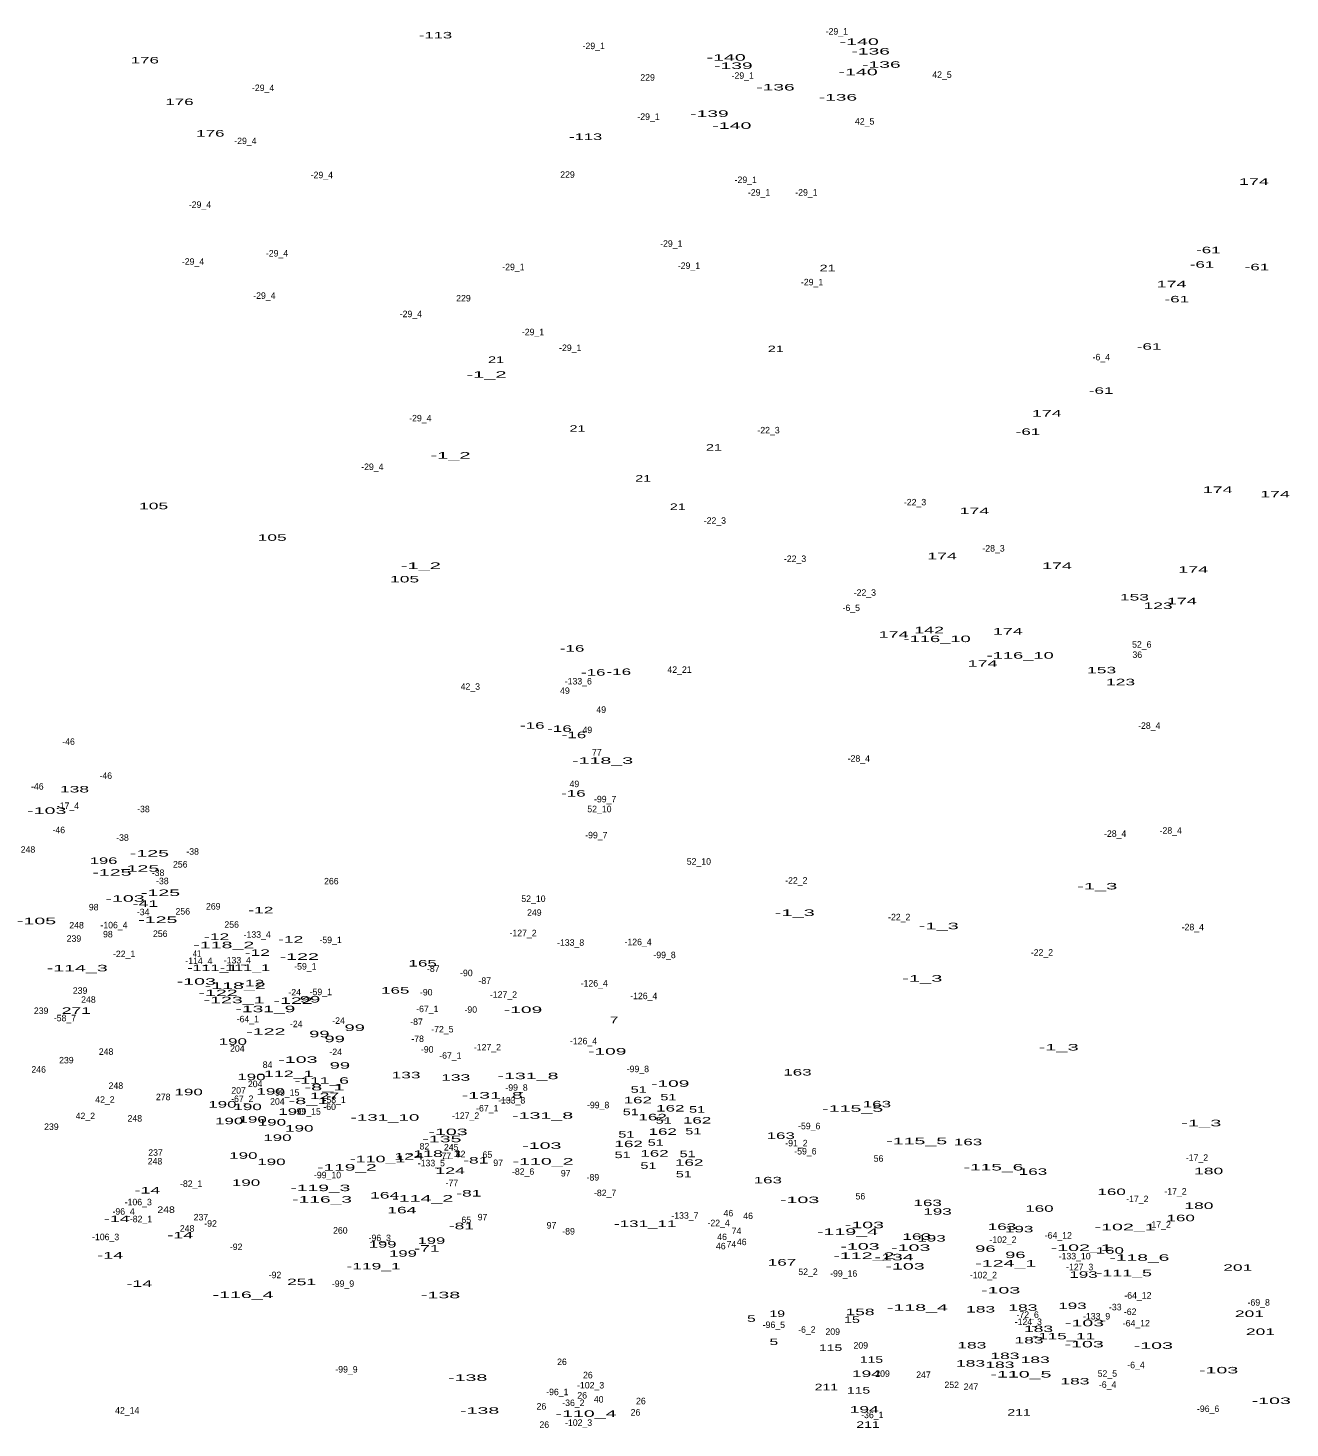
# Model space of a CAD drawing. Extents: x -656096 to -652763, y -1002270 to -998958.
# Drawn here: x -655334 to -654559, y -1000715 to -999855 of the extents above; entities that cross this region are included whole.
import ezdxf
from ezdxf.enums import TextEntityAlignment as Align

# ---------------------------------------------------------------- set-up
doc = ezdxf.new("R2010")
doc.units = 0
doc.header["$LTSCALE"] = 1.6
doc.layers.add('24', color=7, linetype='Continuous')

msp = doc.modelspace()

# ---------------------------------------------------------------- texts
at = {"layer": '24'}
for s, p in [('-29_1', (-654837.412, -999859.48)), ('-29_1', (-654986.682, -999868.4)), ('42_5', (-654772.83, -999886.05)), ('-29_4', (-655189.722, -999894.15)), ('229', (-654953.613, -999887.77)), ('-29_1', (-654895.182, -999886.63)), ('-29_1', (-654953.032, -999911.84)), ('42_5', (-654820.32, -999914.75)), ('-29_4', (-655200.582, -999926.73)), ('-29_4', (-655153.662, -999947.68)), ('229', (-655002.793, -999947.43)), ('-29_1', (-654893.322, -999950.63)), ('-29_1', (-654885.172, -999958.39)), ('-29_1', (-654856.092, -999958.39)), ('-29_4', (-655228.502, -999965.91)), ('-29_4', (-655181.192, -999995.77)), ('-29_1', (-654939.072, -999989.8)), ('-29_4', (-655232.762, -1000000.82)), ('-29_1', (-655036.002, -1000004.16)), ('-29_1', (-654928.212, -1000003.38)), ('-29_1', (-654852.602, -1000013.47)), ('-29_4', (-655188.952, -1000021.76)), ('229', (-655066.693, -1000023.36)), ('-29_4', (-655098.992, -1000033.01)), ('-29_1', (-655023.982, -1000044.11)), ('-29_1', (-655001.112, -1000053.8)), ('-6_4', (-654674.983, -1000059.52)), ('-29_4', (-655093.182, -1000097.01)), ('-22_3', (-654879.332, -1000104.38)), ('-29_4', (-655122.642, -1000126.88)), ('-22_3', (-654789.382, -1000148.6)), ('-22_3', (-654912.292, -1000159.9)), ('-28_3', (-654741.182, -1000176.93)), ('-22_3', (-654863.052, -1000183.36)), ('-22_3', (-654820.202, -1000204.12)), ('-6_5', (-654828.539, -1000213.49)), ('52_6', (-654650.14, -1000235.97)), ('36', (-654652.903, -1000242.28)), ('42_21', (-654934.003, -1000251.42)), ('42_3', (-655062.45, -1000261.81)), ('-133_6', (-654996.162, -1000258.56)), ('49', (-655004.377, -1000264.39)), ('49', (-654982.087, -1000276.02)), ('49', (-654990.617, -1000288.44)), ('-28_4', (-654645.547, -1000285.82)), ('-46', (-655309.195, -1000295.64)), ('77', (-654984.779, -1000302.23)), ('-28_4', (-654823.897, -1000305.99)), ('-46', (-655328.365, -1000323.15)), ('-46', (-655286.345, -1000316.56)), ('49', (-654998.567, -1000321.6)), ('-99_7', (-654979.668, -1000330.95)), ('-17_4', (-655309.566, -1000335.02)), ('-38', (-655263.215, -1000337.04)), ('52_10', (-654983.193, -1000337.04)), ('-46', (-655315.195, -1000349.88)), ('-28_4', (-654632.357, -1000350.21)), ('-38', (-655276.085, -1000354.57)), ('-99_7', (-654985.088, -1000353.06)), ('-28_4', (-654666.477, -1000352.14)), ('248', (-655334.091, -1000361.9)), ('-38', (-655233.005, -1000363.1)), ('256', (-655240.593, -1000371)), ('52_10', (-654922.123, -1000369.24)), ('-38', (-655254.205, -1000376.17)), ('-38', (-655251.595, -1000381.21)), ('266', (-655147.818, -1000381.35)), ('-22_2', (-654862.292, -1000380.9)), ('52_10', (-655023.703, -1000392.12)), ('98', (-655293.763, -1000397.31)), ('-34', (-655263.379, -1000400.27)), ('256', (-655239.043, -1000399.86)), ('269', (-655220.318, -1000396.79)), ('249', (-655023.157, -1000400.63)), ('248', (-655304.271, -1000408.39)), ('-106_4', (-655281.3, -1000408.31)), ('256', (-655209.033, -1000407.99)), ('-22_2', (-654799.092, -1000403.4)), ('-28_4', (-654618.787, -1000409.55)), ('239', (-655305.883, -1000416.57)), ('98', (-655285.043, -1000413.89)), ('256', (-655252.883, -1000413.61)), ('-133_4', (-655193.35, -1000414.09)), ('-59_1', (-655148.282, -1000417.42)), ('-127_2', (-655030.092, -1000413.2)), ('-133_8', (-655000.856, -1000419.04)), ('-126_4', (-654959.456, -1000418.69)), ('-22_1', (-655275.066, -1000425.99)), ('-99_8', (-654943.203, -1000426.64)), ('-22_2', (-654711.462, -1000425.12)), ('-114_4', (-655229.168, -1000430.28)), ('-133_4', (-655205.55, -1000429.88)), ('-59_1', (-655163.772, -1000433.68)), ('-87', (-655085.221, -1000435.08)), ('-90', (-655064.914, -1000437.71)), ('-87', (-655053.621, -1000442.45)), ('-126_4', (-654986.376, -1000444.07)), ('239', (-655302.103, -1000448.53)), ('-24', (-655170.329, -1000449.52)), ('-59_1', (-655154.292, -1000449.37)), ('-90', (-655089.544, -1000449.54)), ('-127_2', (-655042.102, -1000450.97)), ('-126_4', (-654955.976, -1000451.82)), ('239', (-655326.023, -1000460.93)), ('248', (-655296.971, -1000454.04)), ('-67_1', (-655088.867, -1000459.77)), ('-90', (-655062.204, -1000460.2)), ('-58_7', (-655311.408, -1000465.41)), ('-64_1', (-655199.116, -1000466.01)), ('-24', (-655169.359, -1000469.01)), ('-24', (-655143.379, -1000466.98)), ('-87', (-655095.491, -1000467.66)), ('-78', (-655094.831, -1000478.13)), ('-72_5', (-655079.638, -1000472.25)), ('248', (-655286.131, -1000486.01)), ('204', (-655205.545, -1000484.06)), ('-24', (-655145.129, -1000486.18)), ('-90', (-655088.954, -1000484.64)), ('-127_2', (-655051.982, -1000483.32)), ('-126_4', (-654992.956, -1000479.52)), ('239', (-655310.533, -1000491.27)), ('84', (-655187.001, -1000494.07)), ('-67_1', (-655074.727, -1000488.44)), ('246', (-655327.547, -1000496.94)), ('-99_8', (-654959.583, -1000496.65)), ('248', (-655280.131, -1000506.93)), ('207', (-655204.777, -1000509.81)), ('204', (-655194.605, -1000505.85)), ('-99_15', (-655175.777, -1000511.14)), ('-99_8', (-655034.093, -1000508.05)), ('42_2', (-655286.84, -1000515.42)), ('278', (-655251.063, -1000513.86)), ('-67_2', (-655202.494, -1000514.97)), ('204', (-655180.955, -1000516.6)), ('-60', (-655148.854, -1000519.88)), ('-58_1', (-655145.786, -1000515.57)), ('-67_1', (-655052.077, -1000520.79)), ('-133_8', (-655037.066, -1000515.89)), ('-99_8', (-654983.983, -1000518.82)), ('42_2', (-655298.86, -1000525.5)), ('248', (-655268.511, -1000526.99)), ('-99_15', (-655162.597, -1000522.78)), ('-127_2', (-655065.342, -1000525.36)), ('239', (-655319.723, -1000532.12)), ('-59_6', (-654854.373, -1000531.7)), ('237', (-655255.773, -1000547.98)), ('82', (-655090.657, -1000544.14)), ('245', (-655074.201, -1000544.76)), ('-91_2', (-654862.202, -1000542.21)), ('-59_6', (-654856.693, -1000547.2)), ('248', (-655256.121, -1000553.33)), ('-133_5', (-655086.416, -1000554.46)), ('-77', (-655078.085, -1000550.04)), ('82', (-655068.457, -1000548.89)), ('65', (-655051.983, -1000549.26)), ('97', (-655045.398, -1000554.29)), ('56', (-654811.793, -1000551.65)), ('-17_2', (-654616.252, -1000551.07)), ('-99_10', (-655150.161, -1000561.8)), ('-82_6', (-655030.038, -1000559.68)), ('97', (-655003.908, -1000560.69)), ('-89', (-654987.2, -1000563.2)), ('-82_1', (-655233.896, -1000567.11)), ('-77', (-655073.815, -1000566.72)), ('-82_7', (-654979.688, -1000572.77)), ('-17_2', (-654629.442, -1000571.82)), ('-106_3', (-655266.396, -1000578.42)), ('56', (-654822.943, -1000574.82)), ('-17_2', (-654652.902, -1000576.47)), ('-96_4', (-655275.378, -1000584.17)), ('-82_1', (-655264.716, -1000588.82)), ('237', (-655227.893, -1000587.69)), ('65', (-655064.973, -1000589.31)), ('97', (-655054.988, -1000587.65)), ('-133_7', (-654930.692, -1000586.64)), ('46', (-654903.997, -1000585.21)), ('46', (-654891.877, -1000586.86)), ('248', (-655236.371, -1000594.59)), ('-92', (-655221.99, -1000591.55)), ('260', (-655142.297, -1000595.81)), ('97', (-655012.628, -1000592.69)), ('-89', (-655002.13, -1000596.37)), ('-22_4', (-654909.987, -1000591.24)), ('74', (-654899.007, -1000596.11)), ('-64_12', (-654701.386, -1000598.86)), ('-17_2', (-654639.132, -1000592.18)), ('-106_3', (-655286.436, -1000599.82)), ('-92', (-655206.29, -1000605.9)), ('-96_3', (-655118.093, -1000600.41)), ('46', (-654908.657, -1000605.43)), ('46', (-654907.877, -1000599.76)), ('74', (-654902.157, -1000604.31)), ('46', (-654895.807, -1000602.87)), ('-102_2', (-654735.37, -1000601.5)), ('-133_10', (-654691.363, -1000611.62)), ('-92', (-655182.44, -1000623.16)), ('52_2', (-654855.095, -1000621.21)), ('-99_16', (-654833.182, -1000622.25)), ('-102_2', (-654747.39, -1000623.22)), ('-127_3', (-654688.282, -1000618.3)), ('-99_9', (-655140.658, -1000628.48)), ('-64_12', (-654652.516, -1000635.73)), ('-69_8', (-654578.343, -1000640.02)), ('-72_6', (-654720.224, -1000647.55)), ('-133_9', (-654677.882, -1000648.52)), ('-33', (-654666.415, -1000642.9)), ('-62', (-654657.26, -1000645.76)), ('-96_5', (-654876.073, -1000653.77)), ('-6_2', (-654855.799, -1000656.69)), ('209', (-654839.927, -1000657.99)), ('-124_3', (-654719.82, -1000651.93)), ('-64_12', (-654653.486, -1000652.79)), ('209', (-654822.697, -1000666.41)), ('26', (-655006.193, -1000676.51)), ('-99_9', (-655138.528, -1000681.12)), ('26', (-654990.303, -1000684.65)), ('209', (-654809.337, -1000683.75)), ('247', (-654784.187, -1000684.44)), ('52_5', (-654671.275, -1000683.69)), ('-6_4', (-654653.683, -1000678.48)), ('-102_3', (-654988.6, -1000690.88)), ('252', (-654766.837, -1000690.65)), ('247', (-654755.037, -1000691.8)), ('-6_4', (-654671.123, -1000690.5)), ('-96_1', (-655009.047, -1000695.01)), ('-36_2', (-654999.168, -1000701.68)), ('26', (-654993.793, -1000697.07)), ('40', (-654983.655, -1000699.56)), ('26', (-654957.733, -1000700.56)), ('42_14', (-655273.158, -1000706.35)), ('26', (-655018.793, -1000703.85)), ('26', (-654961.023, -1000707.54)), ('-36_1', (-654815.622, -1000709.11)), ('-96_6', (-654609.408, -1000705.33)), ('26', (-655017.053, -1000715.1)), ('-102_3', (-654995.97, -1000713.87))]:
    msp.add_text(s, height=4, dxfattribs=at).set_placement(p, align=Align.CENTER)
for s, width, p in [('-113', 1.9, (-655083.827, -999861.82)), ('-140', 2.25, (-654823.672, -999865.82)), ('176', 1.95, (-655262.387, -999877.19)), ('-140', 2.25, (-654905.382, -999875.51)), ('-136', 2.2, (-654816.595, -999871.71)), ('-139', 2.2, (-654900.905, -999880.56)), ('-140', 2.25, (-654824.342, -999884.42)), ('-136', 2.2, (-654810.015, -999879.84)), ('-136', 2.2, (-654875.075, -999893.79)), ('176', 1.95, (-655241.087, -999902.75)), ('-136', 2.2, (-654836.735, -999899.99)), ('-139', 2.2, (-654915.625, -999910)), ('-140', 2.25, (-654901.892, -999917.35)), ('176', 1.95, (-655222.107, -999922.12)), ('-113', 1.9, (-654991.657, -999924.19)), ('174', 2.05, (-654581.258, -999951.75)), ('-61', 1.95, (-654609.255, -999993.74)), ('21', 1.65, (-654843.097, -1000004.82)), ('-61', 1.95, (-654613.135, -1000002.62)), ('-61', 1.95, (-654579.435, -1000004.2)), ('174', 2.05, (-654631.798, -1000014.67)), ('-61', 1.95, (-654628.625, -1000023.93)), ('21', 1.65, (-654874.887, -1000054.47)), ('-61', 1.95, (-654645.665, -1000052.99)), ('21', 1.65, (-655046.657, -1000061.07)), ('-1_2', 2.3, (-655052.551, -1000070.19)), ('-61', 1.95, (-654675.095, -1000080.1)), ('174', 2.05, (-654708.478, -1000094.08)), ('21', 1.65, (-654996.637, -1000103.34)), ('-61', 1.95, (-654720.015, -1000105.29)), ('21', 1.65, (-654912.887, -1000114.98)), ('-1_2', 2.3, (-655074.651, -1000119.84)), ('21', 1.65, (-654956.317, -1000133.99)), ('174', 2.05, (-654603.528, -1000140.96)), ('174', 2.05, (-654568.288, -1000143.67)), ('105', 2, (-655256.954, -1000150.96)), ('21', 1.65, (-654935.067, -1000151.42)), ('174', 2.05, (-654752.928, -1000153.94)), ('105', 2, (-655184.154, -1000170.34)), ('174', 2.05, (-654772.768, -1000181.64)), ('-1_2', 2.3, (-655092.871, -1000187.6)), ('174', 2.05, (-654702.198, -1000187.64)), ('174', 2.05, (-654618.548, -1000189.97)), ('105', 2, (-655102.824, -1000195.9)), ('153', 2, (-654654.647, -1000206.99)), ('123', 2, (-654640.127, -1000212.21)), ('174', 2.05, (-654625.518, -1000209.34)), ('174', 2.05, (-654802.508, -1000229.87)), ('142', 2.05, (-654780.743, -1000227.15)), ('174', 2.05, (-654732.408, -1000227.93)), ('-16', 1.95, (-654999.975, -1000238.4)), ('-116_10', 2.1, (-654775.825, -1000232.54)), ('-116_10', 2.1, (-654724.805, -1000242.71)), ('-16', 1.95, (-654986.985, -1000253.14)), ('-16', 1.95, (-654971.285, -1000252.75)), ('174', 2.05, (-654747.898, -1000247.69)), ('153', 2, (-654674.787, -1000251.73)), ('123', 2, (-654663.167, -1000259.08)), ('-16', 1.95, (-655024.405, -1000285.72)), ('-16', 1.95, (-655007.725, -1000287.66)), ('-16', 1.95, (-654998.805, -1000291.54)), ('-118_3', 2.25, (-654981.247, -1000307.29)), ('138', 2, (-655305.537, -1000324.88)), ('-16', 1.95, (-654999.195, -1000327.42)), ('-103', 2.25, (-655322.577, -1000338.05)), ('-125', 2.25, (-655259.511, -1000364.25)), ('196', 1.9, (-655287.667, -1000368.76)), ('-125', 2.25, (-655282.561, -1000375.97)), ('-125', 2.25, (-655265.521, -1000373.55)), ('-1_3', 2.3, (-654677.511, -1000384.42)), ('-103', 2.25, (-655274.497, -1000391.97)), ('-125', 2.25, (-655252.741, -1000388.46)), ('-41', 2.05, (-655261.996, -1000395.13)), ('-12', 2, (-655191.121, -1000399.13)), ('-1_3', 2.3, (-654863.241, -1000400.71)), ('-105', 2.25, (-655328.867, -1000405.79)), ('-125', 2.25, (-655254.381, -1000405.03)), ('-1_3', 2.3, (-654774.841, -1000408.85)), ('-12', 2, (-655218.261, -1000415.42)), ('-12', 2, (-655172.801, -1000417.07)), ('41', 0.85, (-655230.309, -1000425.79)), ('-118_2', 2.25, (-655213.867, -1000420.52)), ('-12', 2, (-655193.251, -1000425.22)), ('-122', 2.25, (-655167.521, -1000427.66)), ('-114_3', 2.25, (-655303.863, -1000434.74)), ('-111_1', 1.85, (-655220.93, -1000434.54)), ('-111_1', 1.85, (-655200.88, -1000434.45)), ('165', 1.95, (-655091.723, -1000431.76)), ('-103', 2.25, (-655230.747, -1000442.93)), ('-12', 2, (-655196.741, -1000443.93)), ('-1_3', 2.3, (-654784.921, -1000441.05)), ('-122', 2.25, (-655217.381, -1000449.94)), ('-118_2', 2.25, (-655206.797, -1000445.51)), ('165', 1.95, (-655108.573, -1000448.41)), ('271', 2, (-655304.423, -1000460.84)), ('-123_1', 2.25, (-655207.577, -1000454.3)), ('-131_9', 2.2, (-655188.283, -1000459.81)), ('-122', 2.25, (-655171.291, -1000454.69)), ('99', 2.1, (-655160.891, -1000453.88)), ('-109', 2.2, (-655030.101, -1000460.29)), ('7', 1.8, (-654974.186, -1000466.56)), ('-122', 2.25, (-655188.051, -1000473.67)), ('99', 2.1, (-655155.171, -1000475.21)), ('99', 2.1, (-655145.771, -1000478.22)), ('99', 2.1, (-655133.461, -1000471.33)), ('190', 1.95, (-655208.329, -1000479.85)), ('-109', 2.2, (-654978.401, -1000485.85)), ('-1_3', 2.3, (-654701.171, -1000483.33)), ('-103', 2.25, (-655168.367, -1000490.91)), ('99', 2.1, (-655142.571, -1000494.51)), ('190', 1.95, (-655196.909, -1000501.54)), ('-112_1', 2.05, (-655175.794, -1000499.65)), ('-111_6', 2, (-655153.699, -1000503.75)), ('133', 2, (-655101.947, -1000500.42)), ('133', 2, (-655071.447, -1000501.92)), ('-131_8', 2.25, (-655027.057, -1000500.93)), ('163', 1.95, (-654861.593, -1000498.69)), ('190', 1.95, (-655235.439, -1000510.84)), ('190', 1.95, (-655185.099, -1000510.45)), ('-8_1', 2.3, (-655152.031, -1000507.83)), ('127', 2, (-655152.013, -1000513.2)), ('-131_8', 2.25, (-655049.037, -1000512.84)), ('51', 1.65, (-654959.087, -1000509.29)), ('-109', 2.2, (-654939.731, -1000505.62)), ('190', 1.95, (-655214.719, -1000518.39)), ('190', 1.95, (-655199.229, -1000519.94)), ('-8_1', 2.3, (-655161.821, -1000516.27)), ('162', 1.95, (-654959.623, -1000515.77)), ('162', 1.95, (-654939.673, -1000520.81)), ('51', 1.65, (-654940.867, -1000513.95)), ('51', 1.65, (-654923.227, -1000521.51)), ('-115_5', 2.25, (-654827.667, -1000520.98)), ('163', 1.95, (-654812.793, -1000518.26)), ('190', 1.95, (-655210.559, -1000528.62)), ('190', 1.95, (-655196.129, -1000527.66)), ('190', 1.95, (-655184.319, -1000529.43)), ('190', 1.95, (-655171.729, -1000522.85)), ('-131_10', 2.15, (-655114.87, -1000526.45)), ('-131_8', 2.25, (-655018.057, -1000525.24)), ('51', 1.65, (-654963.937, -1000523.06)), ('162', 1.95, (-654950.523, -1000526.23)), ('51', 1.65, (-654943.767, -1000528.29)), ('162', 1.95, (-654923.223, -1000528.17)), ('-1_3', 2.3, (-654613.581, -1000529.87)), ('190', 1.95, (-655180.929, -1000538.89)), ('190', 1.95, (-655167.469, -1000533.11)), ('-103', 2.25, (-655076.147, -1000535.29)), ('51', 1.65, (-654966.647, -1000536.83)), ('162', 1.95, (-654944.323, -1000535.14)), ('51', 1.65, (-654925.547, -1000534.89)), ('163', 1.95, (-654871.853, -1000537.63)), ('-135', 2.25, (-655079.931, -1000539.66)), ('-103', 2.25, (-655018.567, -1000543.73)), ('162', 1.95, (-654965.233, -1000542.69)), ('51', 1.65, (-654948.617, -1000541.86)), ('-115_5', 2.25, (-654788.357, -1000540.93)), ('163', 1.95, (-654756.833, -1000541.5)), ('190', 1.95, (-655201.839, -1000549.84)), ('190', 1.95, (-655184.609, -1000553.71)), ('-110_1', 2.05, (-655119.43, -1000551.98)), ('124', 2.05, (-655100.053, -1000550.3)), ('-118_1', 2.05, (-655084.144, -1000548.69)), ('-81', 2, (-655059.121, -1000552.74)), ('-110_2', 2.25, (-655017.824, -1000553.41)), ('51', 1.65, (-654968.977, -1000549.43)), ('51', 1.65, (-654953.077, -1000556.03)), ('162', 1.95, (-654949.363, -1000548.5)), ('162', 1.95, (-654928.063, -1000554.12)), ('51', 1.65, (-654929.047, -1000548.86)), ('-119_2', 2.2, (-655138.283, -1000557.1)), ('124', 2.05, (-655074.883, -1000559.12)), ('51', 1.65, (-654931.367, -1000561.26)), ('163', 1.95, (-654879.793, -1000564.94)), ('-115_6', 2.2, (-654741.213, -1000557.01)), ('163', 1.95, (-654716.943, -1000559.71)), ('180', 2, (-654609.054, -1000559.34)), ('-14', 2.05, (-655260.756, -1000571.16)), ('190', 1.95, (-655200.199, -1000566.49)), ('-119_3', 2.2, (-655154.513, -1000569.7)), ('-81', 2, (-655063.391, -1000573.01)), ('160', 1.95, (-654668.649, -1000572.11)), ('-116_3', 2.2, (-655153.473, -1000576.74)), ('164', 2, (-655115.078, -1000574.24)), ('-114_2', 2.25, (-655091.703, -1000576.16)), ('-103', 2.25, (-654860.247, -1000577.04)), ('163', 1.95, (-654781.623, -1000578.89)), ('160', 1.95, (-654712.989, -1000582.38)), ('180', 2, (-654615.054, -1000580.64)), ('-14', 2.05, (-655279.556, -1000588.72)), ('248', 1.2, (-655249.28, -1000583.07)), ('164', 2, (-655104.528, -1000583.34)), ('193', 1.95, (-654775.553, -1000584.21)), ('160', 1.95, (-654626.249, -1000588.19)), ('-14', 2.05, (-655240.596, -1000598.7)), ('-81', 2, (-655067.941, -1000593.08)), ('-131_11', 1.95, (-654955.09, -1000591.72)), ('-119_4', 2.25, (-654830.868, -1000596.62)), ('-103', 2.25, (-654820.477, -1000592.46)), ('163', 1.95, (-654788.393, -1000599.61)), ('163', 1.95, (-654736.013, -1000593.51)), ('193', 1.95, (-654725.423, -1000595.04)), ('-102_1', 2.25, (-654660.374, -1000593.73)), ('199', 1.9, (-655116.287, -1000604.38)), ('-71', 2, (-655089.105, -1000606.87)), ('199', 1.9, (-655086.377, -1000602.11)), ('-103', 2.25, (-654823.187, -1000605.63)), ('-103', 2.25, (-654792.017, -1000606.41)), ('193', 1.95, (-654779.233, -1000600.68)), ('96', 2.1, (-654746.201, -1000607.04)), ('-102_1', 2.25, (-654687.324, -1000606.43)), ('160', 1.95, (-654669.809, -1000608.14)), ('-14', 2.05, (-655283.626, -1000611.12)), ('199', 1.9, (-655103.797, -1000610)), ('167', 1.95, (-654871.077, -1000615.42)), ('-112_2', 2.25, (-654820.797, -1000611.33)), ('-134', 2.25, (-654802.226, -1000612.22)), ('-124_1', 2.25, (-654733.673, -1000616.04)), ('96', 2.1, (-654727.781, -1000610.82)), ('-118_6', 2.2, (-654651.573, -1000612.48)), ('-119_1', 2, (-655121.899, -1000617.8)), ('-103', 2.25, (-654795.497, -1000617.84)), ('193', 1.95, (-654685.923, -1000622.94)), ('-111_5', 2.05, (-654660.954, -1000621.98)), ('201', 2, (-654591.194, -1000618.64)), ('-14', 2.05, (-655265.696, -1000628.47)), ('251', 2, (-655166.087, -1000627.44)), ('-103', 2.25, (-654736.827, -1000632.56)), ('-116_4', 2.25, (-655202.018, -1000635.32)), ('-138', 2.25, (-655080.741, -1000635.48)), ('193', 1.95, (-654692.703, -1000642.12)), ('5', 1.8, (-654889.871, -1000649.96)), ('19', 1.6, (-654874.003, -1000646.95)), ('15', 1.65, (-654828.127, -1000650.62)), ('158', 2, (-654823.147, -1000645.87)), ('-118_4', 2.25, (-654787.933, -1000643.18)), ('183', 2, (-654749.107, -1000644.24)), ('183', 2, (-654723.157, -1000643.18)), ('201', 2, (-654584.034, -1000647)), ('183', 2, (-654713.537, -1000656.26)), ('-103', 2.25, (-654685.317, -1000652.7)), ('201', 2, (-654577.254, -1000658.04)), ('5', 1.8, (-654876.101, -1000664.22)), ('115', 1.6, (-654841.214, -1000667.86)), ('183', 2, (-654754.507, -1000666.33)), ('183', 2, (-654719.387, -1000663.23)), ('-115_11', 1.95, (-654697.99, -1000660.73)), ('-103', 2.25, (-654685.517, -1000665.68)), ('-103', 2.25, (-654643.047, -1000666.53)), ('115', 1.6, (-654816.134, -1000675.13)), ('183', 2, (-654734.177, -1000672.82)), ('183', 2, (-654715.587, -1000675.24)), ('194', 2, (-654819.238, -1000683.84)), ('183', 2, (-654755.287, -1000677.46)), ('183', 2, (-654737.277, -1000678.34)), ('-110_5', 2.25, (-654724.324, -1000684.16)), ('-103', 2.25, (-654602.967, -1000681.64)), ('-138', 2.25, (-655064.081, -1000686.23)), ('211', 1.6, (-654843.844, -1000692.02)), ('115', 1.6, (-654824.074, -1000694.01)), ('183', 2, (-654691.207, -1000688.41)), ('-103', 2.25, (-654570.637, -1000700.43)), ('-138', 2.25, (-655056.731, -1000706.4)), ('-110_4', 2.25, (-654991.429, -1000708.33)), ('194', 2, (-654820.598, -1000705.73)), ('211', 1.6, (-654725.534, -1000707.53)), ('211', 1.6, (-654818.274, -1000715.06))]:
    msp.add_text(s, height=4, dxfattribs=dict(at, width=width)).set_placement(p, align=Align.CENTER)

doc.saveas('drawing.dxf')
